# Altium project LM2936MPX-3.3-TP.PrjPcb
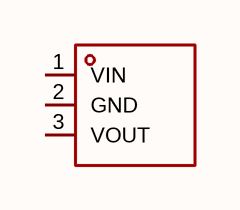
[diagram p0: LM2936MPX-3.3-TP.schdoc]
1 sheet, 1 parts. Net scope: global (net labels, ports and power ports of the same name join across sheets).

## Sheet LM2936MPX-3.3-TP.schdoc
size 127 x 101 mm

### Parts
U?  lm2936mpx-3.3-tp  [SOT-223-3_L6.5-W3.4-P2.30-LS7.0-BR-1]  (value not drawn)

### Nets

Not connected (* = marked no-connect by the designer): U? 1(VIN) 2(GND) 3(VOUT)

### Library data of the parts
U? = lm2936mpx-3.3-tp: 输出极性:正极;工作电压:36V;输出电压:3.3V;输出电流:250mA;电源纹波抑制比(PSRR):70dB@(1kHz);输出类型:固定;; Manufacturer: TECH PUBLIC(台舟); AddInBom: yes; ModelId: 0a360ebfdb9248a182f670f5fd8a68d2; ModelTransform: 275.59,255.905,0,0,0,0,-3.937,0,0; Output Configuration: 正极; Voltage - Supply: 36V; Output Voltage: 3.3V; Output Current: 250mA; Voltage Dropout: 600mV@(100mA); standby current: 2.5uA; Output Type: 固定; Number of Outputs: 1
